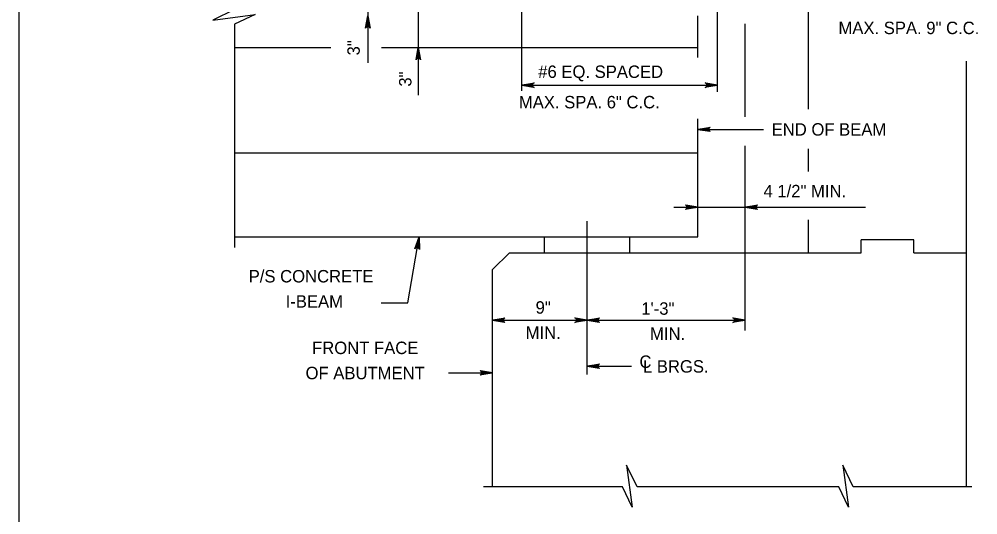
# Model space of a CAD drawing. Extents: x 638653 to 642302, y 298557 to 300414.
# Drawn here: x 640704.2 to 640935.3, y 299388.8 to 299508.4 of the extents above; entities that cross this region are included whole.
import ezdxf

# ---------------------------------------------------------------- set-up
doc = ezdxf.new("R2010")
doc.units = 0
doc.layers.add('1', color=7, linetype='Continuous')

msp = doc.modelspace()

# ---------------------------------------------------------------- linework, layer by layer
at = {"layer": '1'}
for p, q in [((640704.16, 299165.52), (640704.16, 299729.52)), ((640894.51, 299486.71), (640894.51, 299614.65)), ((640788.28, 299531.38), (640788.28, 299497.87)), ((640800.42, 299514.55), (640800.42, 299490.08)), ((640825.36, 299491.12), (640825.36, 299512.83)), ((640872.6, 299490.86), (640872.6, 299512.83)), ((640867.84, 299499.16), (640867.84, 299509.24)), ((640756.09, 299507.21), (640756.09, 299453.34)), ((640879.27, 299484.89), (640879.27, 299507.34)), ((640756.09, 299501.62), (640779.31, 299501.62)), ((640791.51, 299501.62), (640867.84, 299501.62)), ((640932.61, 299452.09), (640932.61, 299498.32)), ((640825.36, 299492.51), (640872.6, 299492.51)), ((640867.84, 299455.9), (640867.84, 299484.37)), ((640867.84, 299481.85), (640883.7, 299481.85)), ((640879.27, 299433.31), (640879.27, 299477.88)), ((640756.09, 299476.22), (640867.84, 299476.22)), ((640894.51, 299471.66), (640894.51, 299477.11)), ((640862.04, 299463.05), (640908.29, 299463.05)), ((640841.17, 299422.69), (640841.17, 299459.72)), ((640894.51, 299452.09), (640894.51, 299459.98)), ((640756.09, 299455.9), (640867.84, 299455.9)), ((640797.89, 299439.96), (640800.66, 299455.9)), ((640830.88, 299452.09), (640830.88, 299455.9)), ((640851.46, 299452.09), (640851.46, 299455.9)), ((640907.21, 299452.09), (640907.21, 299455.21)), ((640919.91, 299455.21), (640907.21, 299455.21)), ((640919.91, 299452.09), (640919.91, 299455.21)), ((640818.31, 299448), (640822.4, 299452.09)), ((640822.4, 299452.09), (640894.51, 299452.09)), ((640894.51, 299452.09), (640907.21, 299452.09)), ((640919.91, 299452.09), (640932.61, 299452.09)), ((640932.61, 299395.62), (640932.61, 299452.09)), ((640818.31, 299395.62), (640818.31, 299448)), ((640791.49, 299439.96), (640797.89, 299439.96)), ((640818.31, 299435.81), (640841.17, 299435.81)), ((640841.17, 299435.81), (640879.27, 299435.81)), ((640841.17, 299424.71), (640851.8, 299424.71)), ((640807.68, 299423.11), (640818.31, 299423.11)), ((640849.66, 299395.62), (640816.17, 299395.62)), ((640901.8, 299395.62), (640853.18, 299395.62)), ((640933.92, 299395.62), (640905.32, 299395.62))]:
    msp.add_line(p, q, dxfattribs=at)
for points in [[(640756.09, 299510.73), (640750.9, 299508.19), (640761.05, 299509.57), (640756.09, 299507.21)], [(640788.28, 299509.24), (640788.84, 299506.26), (640788.76, 299506.37), (640788.68, 299506.49), (640788.58, 299506.54), (640788.48, 299506.6), (640788.38, 299506.62), (640788.28, 299506.64), (640788.18, 299506.62), (640788.08, 299506.6), (640787.98, 299506.54), (640787.88, 299506.49), (640787.8, 299506.37), (640787.72, 299506.26), (640788.28, 299509.24), (640787.8, 299506.37), (640787.88, 299506.49), (640788.28, 299509.24), (640787.98, 299506.54), (640788.08, 299506.6), (640788.28, 299509.24), (640788.18, 299506.62), (640788.28, 299506.64), (640788.28, 299509.24), (640788.38, 299506.62), (640788.48, 299506.6), (640788.28, 299509.24), (640788.58, 299506.54), (640788.68, 299506.49), (640788.28, 299509.24), (640788.76, 299506.37)], [(640800.42, 299501.62), (640800.98, 299498.64), (640800.9, 299498.75), (640800.82, 299498.87), (640800.72, 299498.92), (640800.62, 299498.98), (640800.52, 299499), (640800.42, 299499.02), (640800.32, 299499), (640800.22, 299498.98), (640800.12, 299498.92), (640800.02, 299498.87), (640799.94, 299498.75), (640799.86, 299498.64), (640800.42, 299501.62), (640799.94, 299498.75), (640800.02, 299498.87), (640800.42, 299501.62), (640800.12, 299498.92), (640800.22, 299498.98), (640800.42, 299501.62), (640800.32, 299499), (640800.42, 299499.02), (640800.42, 299501.62), (640800.52, 299499), (640800.62, 299498.98), (640800.42, 299501.62), (640800.72, 299498.92), (640800.82, 299498.87), (640800.42, 299501.62), (640800.9, 299498.75)], [(640825.36, 299492.51), (640828.34, 299493.07), (640828.23, 299492.99), (640828.11, 299492.91), (640828.05, 299492.81), (640827.99, 299492.71), (640827.98, 299492.61), (640827.96, 299492.51), (640827.98, 299492.41), (640827.99, 299492.31), (640828.05, 299492.21), (640828.11, 299492.11), (640828.23, 299492.03), (640828.34, 299491.95), (640825.36, 299492.51), (640828.23, 299492.03), (640828.11, 299492.11), (640825.36, 299492.51), (640828.05, 299492.21), (640827.99, 299492.31), (640825.36, 299492.51), (640827.98, 299492.41), (640827.96, 299492.51), (640825.36, 299492.51), (640827.98, 299492.61), (640827.99, 299492.71), (640825.36, 299492.51), (640828.05, 299492.81), (640828.11, 299492.91), (640825.36, 299492.51), (640828.23, 299492.99)], [(640872.6, 299492.51), (640869.62, 299491.95), (640869.73, 299492.03), (640869.85, 299492.11), (640869.91, 299492.21), (640869.96, 299492.31), (640869.98, 299492.41), (640870, 299492.51), (640869.98, 299492.61), (640869.96, 299492.71), (640869.91, 299492.81), (640869.85, 299492.91), (640869.73, 299492.99), (640869.62, 299493.07), (640872.6, 299492.51), (640869.73, 299492.99), (640869.85, 299492.91), (640872.6, 299492.51), (640869.91, 299492.81), (640869.96, 299492.71), (640872.6, 299492.51), (640869.98, 299492.61), (640870, 299492.51), (640872.6, 299492.51), (640869.98, 299492.41), (640869.96, 299492.31), (640872.6, 299492.51), (640869.91, 299492.21), (640869.85, 299492.11), (640872.6, 299492.51), (640869.73, 299492.03)], [(640867.84, 299481.85), (640870.82, 299482.41), (640870.71, 299482.33), (640870.59, 299482.25), (640870.53, 299482.15), (640870.47, 299482.05), (640870.46, 299481.95), (640870.44, 299481.85), (640870.46, 299481.75), (640870.47, 299481.65), (640870.53, 299481.55), (640870.59, 299481.45), (640870.71, 299481.37), (640870.82, 299481.29), (640867.84, 299481.85), (640870.71, 299481.37), (640870.59, 299481.45), (640867.84, 299481.85), (640870.53, 299481.55), (640870.47, 299481.65), (640867.84, 299481.85), (640870.46, 299481.75), (640870.44, 299481.85), (640867.84, 299481.85), (640870.46, 299481.95), (640870.47, 299482.05), (640867.84, 299481.85), (640870.53, 299482.15), (640870.59, 299482.25), (640867.84, 299481.85), (640870.71, 299482.33)], [(640867.84, 299463.05), (640864.86, 299462.49), (640864.97, 299462.57), (640865.09, 299462.65), (640865.15, 299462.75), (640865.21, 299462.85), (640865.22, 299462.95), (640865.24, 299463.05), (640865.22, 299463.15), (640865.21, 299463.25), (640865.15, 299463.35), (640865.09, 299463.45), (640864.97, 299463.53), (640864.86, 299463.61), (640867.84, 299463.05), (640864.97, 299463.53), (640865.09, 299463.45), (640867.84, 299463.05), (640865.15, 299463.35), (640865.21, 299463.25), (640867.84, 299463.05), (640865.22, 299463.15), (640865.24, 299463.05), (640867.84, 299463.05), (640865.22, 299462.95), (640865.21, 299462.85), (640867.84, 299463.05), (640865.15, 299462.75), (640865.09, 299462.65), (640867.84, 299463.05), (640864.97, 299462.57)], [(640879.27, 299463.05), (640882.25, 299463.61), (640882.14, 299463.53), (640882.02, 299463.45), (640881.96, 299463.35), (640881.9, 299463.25), (640881.89, 299463.15), (640881.87, 299463.05), (640881.89, 299462.95), (640881.9, 299462.85), (640881.96, 299462.75), (640882.02, 299462.65), (640882.14, 299462.57), (640882.25, 299462.49), (640879.27, 299463.05), (640882.14, 299462.57), (640882.02, 299462.65), (640879.27, 299463.05), (640881.96, 299462.75), (640881.9, 299462.85), (640879.27, 299463.05), (640881.89, 299462.95), (640881.87, 299463.05), (640879.27, 299463.05), (640881.89, 299463.15), (640881.9, 299463.25), (640879.27, 299463.05), (640881.96, 299463.35), (640882.02, 299463.45), (640879.27, 299463.05), (640882.14, 299463.53)], [(640800.66, 299455.9), (640800.7, 299452.86), (640800.64, 299452.99), (640800.58, 299453.12), (640800.49, 299453.19), (640800.41, 299453.27), (640800.31, 299453.3), (640800.21, 299453.34), (640800.11, 299453.34), (640800.01, 299453.34), (640799.9, 299453.3), (640799.79, 299453.25), (640799.7, 299453.15), (640799.6, 299453.06), (640800.66, 299455.9), (640799.7, 299453.15), (640799.79, 299453.25), (640800.66, 299455.9), (640799.9, 299453.3), (640800.01, 299453.34), (640800.66, 299455.9), (640800.11, 299453.34), (640800.21, 299453.34), (640800.66, 299455.9), (640800.31, 299453.3), (640800.41, 299453.27), (640800.66, 299455.9), (640800.49, 299453.19), (640800.58, 299453.12), (640800.66, 299455.9), (640800.64, 299452.99)], [(640818.31, 299435.81), (640821.29, 299436.37), (640821.18, 299436.29), (640821.06, 299436.21), (640821, 299436.11), (640820.94, 299436.01), (640820.93, 299435.91), (640820.91, 299435.81), (640820.93, 299435.71), (640820.94, 299435.61), (640821, 299435.51), (640821.06, 299435.41), (640821.18, 299435.33), (640821.29, 299435.25), (640818.31, 299435.81), (640821.18, 299435.33), (640821.06, 299435.41), (640818.31, 299435.81), (640821, 299435.51), (640820.94, 299435.61), (640818.31, 299435.81), (640820.93, 299435.71), (640820.91, 299435.81), (640818.31, 299435.81), (640820.93, 299435.91), (640820.94, 299436.01), (640818.31, 299435.81), (640821, 299436.11), (640821.06, 299436.21), (640818.31, 299435.81), (640821.18, 299436.29)], [(640841.17, 299435.81), (640838.19, 299435.25), (640838.3, 299435.33), (640838.42, 299435.41), (640838.48, 299435.51), (640838.54, 299435.61), (640838.55, 299435.71), (640838.57, 299435.81), (640838.55, 299435.91), (640838.54, 299436.01), (640838.48, 299436.11), (640838.42, 299436.21), (640838.3, 299436.29), (640838.19, 299436.37), (640841.17, 299435.81), (640838.3, 299436.29), (640838.42, 299436.21), (640841.17, 299435.81), (640838.48, 299436.11), (640838.54, 299436.01), (640841.17, 299435.81), (640838.55, 299435.91), (640838.57, 299435.81), (640841.17, 299435.81), (640838.55, 299435.71), (640838.54, 299435.61), (640841.17, 299435.81), (640838.48, 299435.51), (640838.42, 299435.41), (640841.17, 299435.81), (640838.3, 299435.33)], [(640841.17, 299435.81), (640844.15, 299436.37), (640844.04, 299436.29), (640843.92, 299436.21), (640843.86, 299436.11), (640843.8, 299436.01), (640843.79, 299435.91), (640843.77, 299435.81), (640843.79, 299435.71), (640843.8, 299435.61), (640843.86, 299435.51), (640843.92, 299435.41), (640844.04, 299435.33), (640844.15, 299435.25), (640841.17, 299435.81), (640844.04, 299435.33), (640843.92, 299435.41), (640841.17, 299435.81), (640843.86, 299435.51), (640843.8, 299435.61), (640841.17, 299435.81), (640843.79, 299435.71), (640843.77, 299435.81), (640841.17, 299435.81), (640843.79, 299435.91), (640843.8, 299436.01), (640841.17, 299435.81), (640843.86, 299436.11), (640843.92, 299436.21), (640841.17, 299435.81), (640844.04, 299436.29)], [(640879.27, 299435.81), (640876.29, 299435.25), (640876.4, 299435.33), (640876.52, 299435.41), (640876.58, 299435.51), (640876.64, 299435.61), (640876.65, 299435.71), (640876.67, 299435.81), (640876.65, 299435.91), (640876.64, 299436.01), (640876.58, 299436.11), (640876.52, 299436.21), (640876.4, 299436.29), (640876.29, 299436.37), (640879.27, 299435.81), (640876.4, 299436.29), (640876.52, 299436.21), (640879.27, 299435.81), (640876.58, 299436.11), (640876.64, 299436.01), (640879.27, 299435.81), (640876.65, 299435.91), (640876.67, 299435.81), (640879.27, 299435.81), (640876.65, 299435.71), (640876.64, 299435.61), (640879.27, 299435.81), (640876.58, 299435.51), (640876.52, 299435.41), (640879.27, 299435.81), (640876.4, 299435.33)], [(640841.17, 299424.71), (640844.15, 299425.27), (640844.04, 299425.19), (640843.92, 299425.11), (640843.86, 299425.01), (640843.8, 299424.91), (640843.79, 299424.81), (640843.77, 299424.71), (640843.79, 299424.61), (640843.8, 299424.51), (640843.86, 299424.41), (640843.92, 299424.31), (640844.04, 299424.24), (640844.15, 299424.16), (640841.17, 299424.71), (640844.04, 299424.24), (640843.92, 299424.31), (640841.17, 299424.71), (640843.86, 299424.41), (640843.8, 299424.51), (640841.17, 299424.71), (640843.79, 299424.61), (640843.77, 299424.71), (640841.17, 299424.71), (640843.79, 299424.81), (640843.8, 299424.91), (640841.17, 299424.71), (640843.86, 299425.01), (640843.92, 299425.11), (640841.17, 299424.71), (640844.04, 299425.19)], [(640818.31, 299423.11), (640815.33, 299422.55), (640815.44, 299422.63), (640815.56, 299422.71), (640815.62, 299422.81), (640815.68, 299422.91), (640815.69, 299423.01), (640815.71, 299423.11), (640815.69, 299423.21), (640815.68, 299423.31), (640815.62, 299423.41), (640815.56, 299423.51), (640815.44, 299423.59), (640815.33, 299423.67), (640818.31, 299423.11), (640815.44, 299423.59), (640815.56, 299423.51), (640818.31, 299423.11), (640815.62, 299423.41), (640815.68, 299423.31), (640818.31, 299423.11), (640815.69, 299423.21), (640815.71, 299423.11), (640818.31, 299423.11), (640815.69, 299423.01), (640815.68, 299422.91), (640818.31, 299423.11), (640815.62, 299422.81), (640815.56, 299422.71), (640818.31, 299423.11), (640815.44, 299422.63)], [(640853.18, 299395.62), (640850.64, 299400.81), (640852.02, 299390.66), (640849.66, 299395.62)], [(640905.32, 299395.62), (640902.78, 299400.81), (640904.16, 299390.66), (640901.8, 299395.62)]]:
    msp.add_lwpolyline(points, dxfattribs=at)

# ---------------------------------------------------------------- texts
for s, p in [('MAX. SPA. 9" C.C.', (640901.74, 299504.82)), ('#6 EQ. SPACED', (640829.34, 299494.25)), ('MAX. SPA. 6" C.C.', (640824.67, 299486.91)), ('END OF BEAM', (640885.63, 299480.33)), ('4 1/2" MIN.', (640883.66, 299465.45)), ('P/S CONCRETE', (640759.51, 299444.91)), ('I-BEAM', (640768.43, 299438.84)), ('9"', (640828.7, 299437.37)), ('1\'-3"', (640854.19, 299437.12)), ('MIN.', (640826.31, 299431.3)), ('MIN.', (640856.3, 299431.05)), ('FRONT FACE', (640774.8, 299427.63)), ('C', (640853.74, 299424.29)), ('OF ABUTMENT', (640773.23, 299421.56)), ('L BRGS.', (640854.59, 299423.16))]:
    msp.add_text(s, height=3, dxfattribs=at).set_placement(p)
for p in [(640786.3, 299499.68), (640798.76, 299492.15)]:
    msp.add_text('3"', height=3, rotation=90, dxfattribs=at).set_placement(p)

doc.saveas('drawing.dxf')
